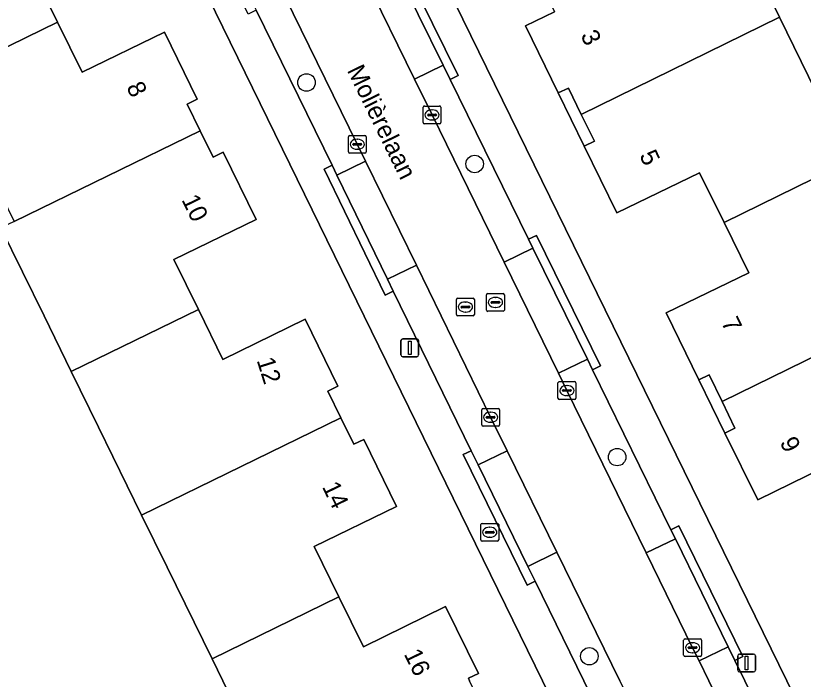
# Model space of a CAD drawing. Extents: x 160455 to 162082, y 388339 to 389736.
# Drawn here: x 160753.79 to 160797.83, y 388750.08 to 388787.22 of the extents above; entities that cross this region are included whole.
import ezdxf

# ---------------------------------------------------------------- set-up
doc = ezdxf.new("R2010")
doc.units = 0
for name, color, linetype in [('IMGEO_Boom', 7, 'Continuous'), ('IMGEO_Brandkraan', 7, 'Continuous'), ('IMGEO_Erf', 7, 'Continuous'), ('IMGEO_Kolk', 7, 'Continuous'), ('IMGEO_Lichtmast', 7, 'Continuous'), ('IMGEO_Openbare_ruimte_label', 7, 'Continuous'), ('IMGEO_Pand', 7, 'Continuous'), ('IMGEO_Pand_nummerreeks', 7, 'Continuous'), ('IMGEO_Parkeervlak_open', 7, 'Continuous'), ('IMGEO_Rijbaan_lokaal_gesloten', 7, 'Continuous'), ('IMGEO_Rioolput', 7, 'Continuous'), ('IMGEO_Voetpad_open', 7, 'Continuous')]:
    doc.layers.add(name, color=color, linetype=linetype)

msp = doc.modelspace()

# ---------------------------------------------------------------- linework, layer by layer
at = {"layer": 'IMGEO_Boom'}
for centre in [(160770.047, 388783.48), (160779.452, 388778.92), (160787.418, 388762.516), (160785.861, 388751.371)]:
    msp.add_circle(centre, 0.489, dxfattribs=at)
at = {"layer": 'IMGEO_Brandkraan'}
for p, q in [((160779.793, 388757.883), (160779.793, 388758.735)), ((160779.868, 388758.809), (160780.72, 388758.809)), ((160780.794, 388758.735), (160780.794, 388757.883)), ((160780.052, 388758.303), (160780.052, 388758.315)), ((160780.49, 388758.266), (160780.092, 388758.266)), ((160780.095, 388758.352), (160780.493, 388758.352)), ((160780.281, 388758.589), (160780.306, 388758.589)), ((160780.536, 388758.315), (160780.536, 388758.303)), ((160780.72, 388757.809), (160779.868, 388757.809)), ((160780.304, 388758.029), (160780.279, 388758.029))]:
    msp.add_line(p, q, dxfattribs=at)
for points in [[(160779.793, 388757.883), (160779.793, 388758.735)], [(160779.868, 388758.809), (160780.72, 388758.809)], [(160780.794, 388758.735), (160780.794, 388757.883)], [(160780.72, 388757.809), (160779.868, 388757.809)]]:
    msp.add_lwpolyline(points, dxfattribs=at)
for centre, radius, start, end in [((160779.87, 388758.733), 0.0765, 91.552, 178.448), ((160779.87, 388758.733), 0.0765, 91.552, 178.448), ((160780.718, 388758.733), 0.0765, 1.552, 88.448), ((160780.718, 388758.733), 0.0765, 1.552, 88.448), ((160780.092, 388758.312), 0.0403, 85.8775, 175.7526), ((160780.089, 388758.302), 0.0366, 178.938, 274.7102), ((160780.493, 388758.309), 0.043, 264.8664, 352.4533), ((160780.497, 388758.314), 0.0386, 1.7309, 96.639), ((160779.87, 388757.885), 0.0765, 181.552, 268.448), ((160779.87, 388757.885), 0.0765, 181.552, 268.448), ((160780.718, 388757.885), 0.0765, 271.552, 358.448), ((160780.718, 388757.885), 0.0765, 271.552, 358.448)]:
    msp.add_arc(centre, radius, start, end, dxfattribs=at)
for centre, major_axis, ratio, start_param, end_param in [((160780.28, 388758.309), (-0.387, 0.002), 0.722429, 4.712389, 7.853982), ((160780.305, 388758.309), (-0.39, 0.002), 0.717154, 1.570796, 4.712389)]:
    msp.add_ellipse(centre, major_axis=major_axis, ratio=ratio, start_param=start_param, end_param=end_param, dxfattribs=at)
at = {"layer": 'IMGEO_Erf'}
for points in [[(160762.403, 388820.913), (160762.283, 388820.813), (160769.045, 388806.982), (160773.503, 388797.864), (160796.902, 388750), (160806.284, 388730.808)], [(160798.94, 388717.887), (160783.242, 388750), (160751.22, 388815.507)], [(160794.101, 388792.028), (160796.497, 388787.131), (160798.923, 388782.173)], [(160754.753, 388789.659), (160756.132, 388786.849), (160757.504, 388784.052), (160762.105, 388786.298), (160763.937, 388782.546), (160763.371, 388782.269), (160764.101, 388780.783), (160764.824, 388779.31), (160765.39, 388779.587), (160767.23, 388775.821), (160762.63, 388773.573), (160763.999, 388770.779), (160765.372, 388767.978), (160769.972, 388770.227), (160771.803, 388766.479), (160771.237, 388766.202), (160771.966, 388764.711), (160772.688, 388763.234), (160773.254, 388763.51), (160775.082, 388759.759), (160770.479, 388757.517), (160771.857, 388754.704), (160773.231, 388751.898), (160777.828, 388754.153), (160779.662, 388750.414), (160779.097, 388750.136), (160779.163, 388750)], [(160799.891, 388762.386), (160795.278, 388760.118), (160793.436, 388763.863), (160791.989, 388766.839), (160790.163, 388770.583), (160794.784, 388772.835), (160793.401, 388775.643), (160792.029, 388778.429), (160787.408, 388776.179), (160785.583, 388779.926), (160784.123, 388782.893), (160782.292, 388786.652), (160783.913, 388787.442)], [(160778.747, 388724.517), (160777.293, 388727.489), (160774.889, 388732.4), (160774.153, 388732.04), (160772.633, 388735.146), (160770.115, 388740.29), (160772.314, 388741.367), (160770.895, 388744.266), (160768.487, 388749.186), (160766.288, 388748.11), (160765.363, 388750), (160764.763, 388751.225), (160762.25, 388756.361), (160760.825, 388759.272), (160758.418, 388764.189), (160756.893, 388767.305), (160755.369, 388770.42), (160752.96, 388775.341)]]:
    msp.add_lwpolyline(points, dxfattribs=at)
for points in [[(160785.583, 388779.926), (160786.149, 388780.202), (160785.414, 388781.697), (160784.69, 388783.169), (160784.123, 388782.893)], [(160793.436, 388763.863), (160794.002, 388764.141), (160793.282, 388765.62), (160792.555, 388767.115), (160791.989, 388766.839)]]:
    msp.add_lwpolyline(points, close=True, dxfattribs=at)
at = {"layer": 'IMGEO_Kolk'}
for p, q in [((160776.566, 388781.239), (160776.566, 388782.091)), ((160776.641, 388782.165), (160777.493, 388782.165)), ((160777.567, 388782.091), (160777.567, 388781.239)), ((160776.825, 388781.659), (160776.825, 388781.671)), ((160777.263, 388781.622), (160776.865, 388781.622)), ((160776.868, 388781.708), (160777.266, 388781.708)), ((160777.054, 388781.945), (160777.079, 388781.945)), ((160777.309, 388781.671), (160777.309, 388781.659)), ((160777.493, 388781.165), (160776.641, 388781.165)), ((160777.077, 388781.385), (160777.052, 388781.385)), ((160772.387, 388779.595), (160772.387, 388780.447)), ((160772.462, 388780.521), (160773.314, 388780.521)), ((160772.875, 388780.301), (160772.9, 388780.301)), ((160773.388, 388780.447), (160773.388, 388779.595)), ((160772.646, 388780.015), (160772.646, 388780.027)), ((160773.084, 388779.978), (160772.686, 388779.978)), ((160772.689, 388780.064), (160773.087, 388780.064)), ((160773.13, 388780.027), (160773.13, 388780.015)), ((160773.314, 388779.521), (160772.462, 388779.521)), ((160772.898, 388779.741), (160772.873, 388779.741)), ((160784.11, 388765.814), (160784.11, 388766.666)), ((160784.185, 388766.74), (160785.037, 388766.74)), ((160785.111, 388766.666), (160785.111, 388765.814)), ((160784.369, 388766.234), (160784.369, 388766.246)), ((160784.807, 388766.197), (160784.409, 388766.197)), ((160784.412, 388766.283), (160784.81, 388766.283)), ((160784.598, 388766.52), (160784.623, 388766.52)), ((160784.853, 388766.246), (160784.853, 388766.234)), ((160785.037, 388765.74), (160784.185, 388765.74)), ((160784.621, 388765.96), (160784.596, 388765.96)), ((160779.844, 388764.318), (160779.844, 388765.17)), ((160779.919, 388765.244), (160780.771, 388765.244)), ((160780.332, 388765.024), (160780.357, 388765.024)), ((160780.845, 388765.17), (160780.845, 388764.318)), ((160780.103, 388764.738), (160780.103, 388764.75)), ((160780.541, 388764.701), (160780.143, 388764.701)), ((160780.146, 388764.787), (160780.544, 388764.787)), ((160780.355, 388764.464), (160780.33, 388764.464)), ((160780.587, 388764.75), (160780.587, 388764.738)), ((160780.771, 388764.244), (160779.919, 388764.244)), ((160791.138, 388751.424), (160791.138, 388752.276)), ((160791.213, 388752.35), (160792.065, 388752.35)), ((160791.626, 388752.13), (160791.651, 388752.13)), ((160792.139, 388752.276), (160792.139, 388751.424)), ((160791.397, 388751.844), (160791.397, 388751.856)), ((160791.835, 388751.807), (160791.437, 388751.807)), ((160791.44, 388751.893), (160791.838, 388751.893)), ((160791.881, 388751.856), (160791.881, 388751.844)), ((160792.065, 388751.35), (160791.213, 388751.35)), ((160791.649, 388751.57), (160791.624, 388751.57))]:
    msp.add_line(p, q, dxfattribs=at)
for points in [[(160776.566, 388781.239), (160776.566, 388782.091)], [(160776.641, 388782.165), (160777.493, 388782.165)], [(160777.567, 388782.091), (160777.567, 388781.239)], [(160777.493, 388781.165), (160776.641, 388781.165)], [(160772.387, 388779.595), (160772.387, 388780.447)], [(160772.462, 388780.521), (160773.314, 388780.521)], [(160773.388, 388780.447), (160773.388, 388779.595)], [(160773.314, 388779.521), (160772.462, 388779.521)], [(160784.11, 388765.814), (160784.11, 388766.666)], [(160784.185, 388766.74), (160785.037, 388766.74)], [(160785.111, 388766.666), (160785.111, 388765.814)], [(160785.037, 388765.74), (160784.185, 388765.74)], [(160779.844, 388764.318), (160779.844, 388765.17)], [(160779.919, 388765.244), (160780.771, 388765.244)], [(160780.845, 388765.17), (160780.845, 388764.318)], [(160780.771, 388764.244), (160779.919, 388764.244)], [(160791.138, 388751.424), (160791.138, 388752.276)], [(160791.213, 388752.35), (160792.065, 388752.35)], [(160792.139, 388752.276), (160792.139, 388751.424)], [(160792.065, 388751.35), (160791.213, 388751.35)]]:
    msp.add_lwpolyline(points, dxfattribs=at)
for centre, radius, start, end in [((160776.643, 388782.089), 0.0765, 91.552, 178.448), ((160776.643, 388782.089), 0.0765, 91.552, 178.448), ((160777.491, 388782.089), 0.0765, 1.552, 88.448), ((160777.491, 388782.089), 0.0765, 1.552, 88.448), ((160776.865, 388781.668), 0.0403, 85.8775, 175.7526), ((160776.862, 388781.658), 0.0366, 178.938, 274.7102), ((160777.266, 388781.665), 0.043, 264.8664, 352.4533), ((160777.27, 388781.67), 0.0386, 1.7309, 96.639), ((160776.643, 388781.241), 0.0765, 181.552, 268.448), ((160776.643, 388781.241), 0.0765, 181.552, 268.448), ((160777.491, 388781.241), 0.0765, 271.552, 358.448), ((160777.491, 388781.241), 0.0765, 271.552, 358.448), ((160772.464, 388780.445), 0.0765, 91.552, 178.448), ((160772.464, 388780.445), 0.0765, 91.552, 178.448), ((160773.312, 388780.445), 0.0765, 1.552, 88.448), ((160773.312, 388780.445), 0.0765, 1.552, 88.448), ((160772.686, 388780.024), 0.0403, 85.8775, 175.7526), ((160772.683, 388780.014), 0.0366, 178.938, 274.7102), ((160773.087, 388780.021), 0.043, 264.8664, 352.4533), ((160773.091, 388780.026), 0.0386, 1.7309, 96.639), ((160772.464, 388779.597), 0.0765, 181.552, 268.448), ((160772.464, 388779.597), 0.0765, 181.552, 268.448), ((160773.312, 388779.597), 0.0765, 271.552, 358.448), ((160773.312, 388779.597), 0.0765, 271.552, 358.448), ((160784.187, 388766.664), 0.0765, 91.552, 178.448), ((160784.187, 388766.664), 0.0765, 91.552, 178.448), ((160785.035, 388766.664), 0.0765, 1.552, 88.448), ((160785.035, 388766.664), 0.0765, 1.552, 88.448), ((160784.409, 388766.243), 0.0403, 85.8775, 175.7526), ((160784.406, 388766.233), 0.0366, 178.938, 274.7102), ((160784.81, 388766.24), 0.043, 264.8664, 352.4533), ((160784.814, 388766.245), 0.0386, 1.7309, 96.639), ((160784.187, 388765.816), 0.0765, 181.552, 268.448), ((160784.187, 388765.816), 0.0765, 181.552, 268.448), ((160785.035, 388765.816), 0.0765, 271.552, 358.448), ((160785.035, 388765.816), 0.0765, 271.552, 358.448), ((160779.921, 388765.168), 0.0765, 91.552, 178.448), ((160779.921, 388765.168), 0.0765, 91.552, 178.448), ((160780.769, 388765.168), 0.0765, 1.552, 88.448), ((160780.769, 388765.168), 0.0765, 1.552, 88.448), ((160780.143, 388764.747), 0.0403, 85.8775, 175.7526), ((160780.14, 388764.737), 0.0366, 178.938, 274.7102), ((160780.544, 388764.744), 0.043, 264.8664, 352.4533), ((160780.548, 388764.749), 0.0386, 1.7309, 96.639), ((160779.921, 388764.32), 0.0765, 181.552, 268.448), ((160779.921, 388764.32), 0.0765, 181.552, 268.448), ((160780.769, 388764.32), 0.0765, 271.552, 358.448), ((160780.769, 388764.32), 0.0765, 271.552, 358.448), ((160791.215, 388752.274), 0.0765, 91.552, 178.448), ((160791.215, 388752.274), 0.0765, 91.552, 178.448), ((160792.063, 388752.274), 0.0765, 1.552, 88.448), ((160792.063, 388752.274), 0.0765, 1.552, 88.448), ((160791.437, 388751.853), 0.0403, 85.8775, 175.7526), ((160791.434, 388751.843), 0.0366, 178.938, 274.7102), ((160791.838, 388751.85), 0.043, 264.8664, 352.4533), ((160791.842, 388751.855), 0.0386, 1.7309, 96.639), ((160791.215, 388751.426), 0.0765, 181.552, 268.448), ((160791.215, 388751.426), 0.0765, 181.552, 268.448), ((160792.063, 388751.426), 0.0765, 271.552, 358.448), ((160792.063, 388751.426), 0.0765, 271.552, 358.448)]:
    msp.add_arc(centre, radius, start, end, dxfattribs=at)
for centre, major_axis, ratio, start_param, end_param in [((160777.053, 388781.665), (-0.387, 0.002), 0.722429, 4.712389, 7.853982), ((160777.078, 388781.665), (-0.39, 0.002), 0.717154, 1.570796, 4.712389), ((160772.874, 388780.021), (-0.387, 0.002), 0.722429, 4.712389, 7.853982), ((160772.899, 388780.021), (-0.39, 0.002), 0.717154, 1.570796, 4.712389), ((160784.597, 388766.24), (-0.387, 0.002), 0.722429, 4.712389, 7.853982), ((160784.622, 388766.24), (-0.39, 0.002), 0.717154, 1.570796, 4.712389), ((160780.331, 388764.744), (-0.387, 0.002), 0.722429, 4.712389, 7.853982), ((160780.356, 388764.744), (-0.39, 0.002), 0.717154, 1.570796, 4.712389), ((160791.625, 388751.85), (-0.387, 0.002), 0.722429, 4.712389, 7.853982), ((160791.65, 388751.85), (-0.39, 0.002), 0.717154, 1.570796, 4.712389)]:
    msp.add_ellipse(centre, major_axis=major_axis, ratio=ratio, start_param=start_param, end_param=end_param, dxfattribs=at)
at = {"layer": 'IMGEO_Lichtmast'}
for p, q in [((160775.329, 388768.235), (160775.329, 388769.035)), ((160775.329, 388769.035), (160775.329, 388768.235)), ((160775.429, 388769.135), (160776.219, 388769.135)), ((160776.219, 388769.135), (160775.429, 388769.135)), ((160776.319, 388769.035), (160776.319, 388768.235)), ((160776.319, 388768.235), (160776.319, 388769.035)), ((160776.219, 388768.135), (160775.429, 388768.135)), ((160775.429, 388768.135), (160776.219, 388768.135)), ((160794.158, 388750.593), (160794.158, 388751.393)), ((160794.158, 388751.393), (160794.158, 388750.593)), ((160794.258, 388751.493), (160795.048, 388751.493)), ((160795.048, 388751.493), (160794.258, 388751.493)), ((160795.148, 388751.393), (160795.148, 388750.593)), ((160795.148, 388750.593), (160795.148, 388751.393)), ((160795.048, 388750.493), (160794.258, 388750.493)), ((160794.258, 388750.493), (160795.048, 388750.493))]:
    msp.add_line(p, q, dxfattribs=at)
for points in [[(160775.749, 388769.01), (160775.899, 388769.01), (160775.899, 388768.26), (160775.749, 388768.26), (160775.749, 388769.01)], [(160794.578, 388751.368), (160794.728, 388751.368), (160794.728, 388750.618), (160794.578, 388750.618), (160794.578, 388751.368)]]:
    msp.add_lwpolyline(points, dxfattribs=at)
for centre, start, end in [((160775.429, 388769.035), 90, 180), ((160775.429, 388769.035), 90, 180), ((160776.219, 388769.035), 0, 90), ((160776.219, 388769.035), 360, 90), ((160775.429, 388768.235), 180, 270), ((160775.429, 388768.235), 180, 270), ((160776.219, 388768.235), 270, 0), ((160776.219, 388768.235), 270, 0), ((160794.258, 388751.393), 90, 180), ((160794.258, 388751.393), 90, 180), ((160795.048, 388751.393), 0, 90), ((160795.048, 388751.393), 360, 90), ((160794.258, 388750.593), 180, 270), ((160794.258, 388750.593), 180, 270), ((160795.048, 388750.593), 270, 0), ((160795.048, 388750.593), 270, 0)]:
    msp.add_arc(centre, 0.1, start, end, dxfattribs=at)
at = {"layer": 'IMGEO_Pand'}
for points in [[(160749.025, 388783.384), (160756.132, 388786.849), (160754.753, 388789.659), (160759.355, 388791.904), (160757.521, 388795.663), (160756.954, 388795.387), (160756.237, 388796.855), (160747.282, 388792.491), (160749.69, 388787.572), (160747.5, 388786.499)], [(160792.571, 388795.154), (160785.541, 388791.701), (160782.547, 388790.23), (160783.913, 388787.442), (160782.292, 388786.652), (160784.123, 388782.893), (160784.69, 388783.169), (160785.414, 388781.697), (160796.497, 388787.131), (160794.101, 388792.028)], [(160749.025, 388783.384), (160751.538, 388778.249), (160752.274, 388778.609), (160753.697, 388775.7), (160764.101, 388780.783), (160763.371, 388782.269), (160763.937, 388782.546), (160762.105, 388786.298), (160757.504, 388784.052), (160756.132, 388786.849)], [(160796.497, 388787.131), (160785.414, 388781.697), (160786.149, 388780.202), (160785.583, 388779.926), (160787.408, 388776.179), (160792.029, 388778.429), (160793.401, 388775.643), (160800.43, 388779.094), (160798.923, 388782.173)], [(160756.893, 388767.305), (160763.999, 388770.779), (160762.63, 388773.573), (160767.23, 388775.821), (160765.39, 388779.587), (160764.824, 388779.31), (160764.101, 388780.783), (160753.697, 388775.7), (160752.96, 388775.341), (160755.369, 388770.42)], [(160793.401, 388775.643), (160794.784, 388772.835), (160790.163, 388770.583), (160791.989, 388766.839), (160792.555, 388767.115), (160793.282, 388765.62), (160804.365, 388771.054), (160801.966, 388775.955), (160800.43, 388779.094)], [(160804.365, 388771.054), (160793.282, 388765.62), (160794.002, 388764.141), (160793.436, 388763.863), (160795.278, 388760.118), (160799.891, 388762.386), (160801.263, 388759.574), (160808.294, 388763.025), (160811.219, 388764.461), (160807.288, 388772.495)], [(160756.893, 388767.305), (160758.418, 388764.189), (160760.825, 388759.272), (160771.966, 388764.711), (160771.237, 388766.202), (160771.803, 388766.479), (160769.972, 388770.227), (160765.372, 388767.978), (160763.999, 388770.779)], [(160771.857, 388754.704), (160770.479, 388757.517), (160775.082, 388759.759), (160773.254, 388763.51), (160772.688, 388763.234), (160771.966, 388764.711), (160760.825, 388759.272), (160762.25, 388756.361), (160764.763, 388751.225)], [(160771.857, 388754.704), (160764.763, 388751.225), (160765.363, 388750), (160766.288, 388748.11), (160768.487, 388749.186), (160770.895, 388744.266), (160779.827, 388748.636), (160779.163, 388750), (160779.097, 388750.136), (160779.662, 388750.414), (160777.828, 388754.153), (160773.231, 388751.898)]]:
    msp.add_lwpolyline(points, close=True, dxfattribs=at)
at = {"layer": 'IMGEO_Parkeervlak_open'}
for points in [[(160774.897, 388790.136), (160773.301, 388789.354), (160776.082, 388783.674), (160777.681, 388784.457)], [(160768.406, 388789.196), (160766.803, 388788.413), (160767.24, 388787.521), (160771.476, 388778.85), (160771.742, 388778.301), (160773.346, 388779.084), (160772.889, 388780.021)], [(160778.078, 388783.647), (160777.681, 388784.457), (160776.082, 388783.674), (160777.066, 388781.664), (160781.099, 388773.419), (160782.707, 388774.206), (160782.463, 388774.704)], [(160773.346, 388779.084), (160771.742, 388778.301), (160774.575, 388772.466), (160776.191, 388773.256)], [(160782.707, 388774.206), (160781.099, 388773.419), (160784.136, 388767.21), (160785.752, 388768)], [(160776.191, 388773.256), (160774.575, 388772.466), (160774.898, 388771.8), (160779.263, 388762.876), (160779.654, 388762.076), (160781.266, 388762.866), (160780.345, 388764.745)], [(160786.046, 388767.401), (160785.752, 388768), (160784.136, 388767.21), (160784.61, 388766.24), (160789.047, 388757.155), (160790.673, 388757.95), (160790.427, 388758.453)], [(160781.266, 388762.866), (160779.654, 388762.076), (160782.431, 388756.399), (160784.046, 388757.191)], [(160790.673, 388757.95), (160789.047, 388757.155), (160791.638, 388751.849), (160792, 388751.11), (160793.623, 388751.905)], [(160784.046, 388757.191), (160782.431, 388756.399), (160782.839, 388755.564), (160785.561, 388750), (160787.221, 388746.607), (160787.583, 388745.867), (160789.2, 388746.653), (160787.869, 388749.389), (160787.57, 388750)], [(160794.551, 388750), (160794, 388751.132), (160793.623, 388751.905), (160792, 388751.11), (160792.544, 388750), (160797.021, 388740.864), (160798.623, 388741.649), (160798.231, 388742.445)]]:
    msp.add_lwpolyline(points, close=True, dxfattribs=at)
at = {"layer": 'IMGEO_Rijbaan_lokaal_gesloten'}
for points in [[(160768.406, 388789.196), (160772.889, 388780.021), (160773.346, 388779.084), (160776.191, 388773.256), (160780.345, 388764.745), (160781.266, 388762.866), (160784.046, 388757.191), (160787.57, 388750), (160787.869, 388749.389), (160789.2, 388746.653), (160792.011, 388740.874), (160795.768, 388733.152), (160796.496, 388731.738), (160796.586, 388731.565), (160800.932, 388722.63)], [(160799.905, 388734.979), (160797.021, 388740.864), (160792.544, 388750), (160792, 388751.11), (160791.638, 388751.849), (160789.047, 388757.155), (160784.61, 388766.24), (160784.136, 388767.21), (160781.099, 388773.419), (160777.066, 388781.664), (160776.082, 388783.674), (160773.301, 388789.354)]]:
    msp.add_lwpolyline(points, dxfattribs=at)
at = {"layer": 'IMGEO_Rioolput'}
for p, q in [((160778.509, 388771.416), (160779.361, 388771.416)), ((160780.111, 388770.748), (160780.111, 388771.6)), ((160780.186, 388771.674), (160781.038, 388771.674)), ((160780.599, 388771.454), (160780.624, 388771.454)), ((160781.112, 388771.6), (160781.112, 388770.748)), ((160778.434, 388770.49), (160778.434, 388771.342)), ((160778.922, 388771.196), (160778.947, 388771.196)), ((160779.435, 388771.342), (160779.435, 388770.49)), ((160780.37, 388771.168), (160780.37, 388771.18)), ((160780.808, 388771.131), (160780.41, 388771.131)), ((160780.413, 388771.217), (160780.811, 388771.217)), ((160780.854, 388771.18), (160780.854, 388771.168)), ((160778.693, 388770.91), (160778.693, 388770.922)), ((160779.131, 388770.873), (160778.733, 388770.873)), ((160778.736, 388770.959), (160779.134, 388770.959)), ((160778.945, 388770.636), (160778.92, 388770.636)), ((160779.177, 388770.922), (160779.177, 388770.91)), ((160781.038, 388770.674), (160780.186, 388770.674)), ((160780.622, 388770.894), (160780.597, 388770.894)), ((160779.361, 388770.416), (160778.509, 388770.416))]:
    msp.add_line(p, q, dxfattribs=at)
for points in [[(160778.509, 388771.416), (160779.361, 388771.416)], [(160780.111, 388770.748), (160780.111, 388771.6)], [(160780.186, 388771.674), (160781.038, 388771.674)], [(160781.112, 388771.6), (160781.112, 388770.748)], [(160778.434, 388770.49), (160778.434, 388771.342)], [(160779.435, 388771.342), (160779.435, 388770.49)], [(160781.038, 388770.674), (160780.186, 388770.674)], [(160779.361, 388770.416), (160778.509, 388770.416)]]:
    msp.add_lwpolyline(points, dxfattribs=at)
for centre, radius, start, end in [((160778.511, 388771.34), 0.0765, 91.552, 178.448), ((160778.511, 388771.34), 0.0765, 91.552, 178.448), ((160779.359, 388771.34), 0.0765, 1.552, 88.448), ((160779.359, 388771.34), 0.0765, 1.552, 88.448), ((160780.188, 388771.598), 0.0765, 91.552, 178.448), ((160780.188, 388771.598), 0.0765, 91.552, 178.448), ((160781.036, 388771.598), 0.0765, 1.552, 88.448), ((160781.036, 388771.598), 0.0765, 1.552, 88.448), ((160780.41, 388771.177), 0.0403, 85.8775, 175.7526), ((160780.407, 388771.167), 0.0366, 178.938, 274.7102), ((160780.811, 388771.174), 0.043, 264.8664, 352.4533), ((160780.815, 388771.179), 0.0386, 1.7309, 96.639), ((160778.733, 388770.919), 0.0403, 85.8775, 175.7526), ((160778.73, 388770.909), 0.0366, 178.938, 274.7102), ((160779.134, 388770.916), 0.043, 264.8664, 352.4533), ((160779.138, 388770.921), 0.0386, 1.7309, 96.639), ((160780.188, 388770.75), 0.0765, 181.552, 268.448), ((160780.188, 388770.75), 0.0765, 181.552, 268.448), ((160781.036, 388770.75), 0.0765, 271.552, 358.448), ((160781.036, 388770.75), 0.0765, 271.552, 358.448), ((160778.511, 388770.492), 0.0765, 181.552, 268.448), ((160778.511, 388770.492), 0.0765, 181.552, 268.448), ((160779.359, 388770.492), 0.0765, 271.552, 358.448), ((160779.359, 388770.492), 0.0765, 271.552, 358.448)]:
    msp.add_arc(centre, radius, start, end, dxfattribs=at)
for centre, major_axis, ratio, start_param, end_param in [((160780.598, 388771.174), (-0.387, 0.002), 0.722429, 4.712389, 7.853982), ((160780.623, 388771.174), (-0.39, 0.002), 0.717154, 1.570796, 4.712389), ((160778.921, 388770.916), (-0.387, 0.002), 0.722429, 4.712389, 7.853982), ((160778.946, 388770.916), (-0.39, 0.002), 0.717154, 1.570796, 4.712389)]:
    msp.add_ellipse(centre, major_axis=major_axis, ratio=ratio, start_param=start_param, end_param=end_param, dxfattribs=at)
at = {"layer": 'IMGEO_Voetpad_open'}
for points in [[(160806.284, 388730.808), (160796.902, 388750), (160773.503, 388797.864), (160769.045, 388806.982), (160762.283, 388820.813), (160762.403, 388820.913)], [(160762.271, 388815.955), (160774.49, 388790.966), (160774.938, 388791.186), (160778.526, 388783.867), (160778.078, 388783.647), (160782.463, 388774.704), (160782.911, 388774.924), (160786.494, 388767.621), (160786.046, 388767.401), (160790.427, 388758.453), (160790.876, 388758.672), (160794.449, 388751.351), (160794, 388751.132), (160794.551, 388750), (160798.231, 388742.445), (160798.679, 388742.665), (160802.333, 388735.248), (160801.885, 388735.028)], [(160751.22, 388815.507), (160783.242, 388750), (160798.94, 388717.887), (160796.193, 388716.592), (160796.096, 388716.524), (160796.229, 388716.231), (160787.552, 388711.973), (160789.992, 388706.936), (160811.085, 388717.249), (160809.661, 388720.335), (160800.591, 388722.19), (160796.035, 388731.513), (160796.496, 388731.738)], [(160793.577, 388733.616), (160790.788, 388739.318), (160790.34, 388739.099), (160786.774, 388746.389), (160787.221, 388746.607), (160785.561, 388750), (160782.839, 388755.564), (160782.39, 388755.345), (160778.813, 388762.657), (160779.263, 388762.876), (160774.898, 388771.8), (160774.449, 388771.582), (160771.027, 388778.632), (160771.476, 388778.85), (160767.24, 388787.521), (160766.791, 388787.302), (160763.204, 388794.629), (160763.653, 388794.848), (160759.281, 388803.764), (160758.29, 388803.286), (160756.18, 388807.657), (160757.171, 388808.135), (160755.331, 388811.883)]]:
    msp.add_lwpolyline(points, dxfattribs=at)
for points in [[(160774.938, 388791.186), (160774.49, 388790.966), (160774.897, 388790.136), (160777.681, 388784.457), (160778.078, 388783.647), (160778.526, 388783.867)], [(160771.742, 388778.301), (160771.476, 388778.85), (160771.027, 388778.632), (160774.449, 388771.582), (160774.898, 388771.8), (160774.575, 388772.466)], [(160782.911, 388774.924), (160782.463, 388774.704), (160782.707, 388774.206), (160785.752, 388768), (160786.046, 388767.401), (160786.494, 388767.621)], [(160779.654, 388762.076), (160779.263, 388762.876), (160778.813, 388762.657), (160782.39, 388755.345), (160782.839, 388755.564), (160782.431, 388756.399)], [(160790.876, 388758.672), (160790.427, 388758.453), (160790.673, 388757.95), (160793.623, 388751.905), (160794, 388751.132), (160794.449, 388751.351)]]:
    msp.add_lwpolyline(points, close=True, dxfattribs=at)

# ---------------------------------------------------------------- texts
at = {"layer": 'IMGEO_Openbare_ruimte_label'}
msp.add_text('Molièrelaan', height=1, rotation=296.1553, dxfattribs=at).set_placement((160772.292, 388784.164))
at = {"layer": 'IMGEO_Pand_nummerreeks'}
for s, rotation, p in [('3', 295.972, (160785.353, 388786.123)), ('8', 296.025, (160759.955, 388783.227)), ('5', 295.9687, (160788.641, 388779.403)), ('10', 296.0393, (160763.041, 388776.922)), ('7', 295.9991, (160793.221, 388770.063)), ('12', 287.4472, (160767.254, 388767.936)), ('9', 296.1897, (160796.496, 388763.349)), ('14', 295.9817, (160770.898, 388760.858)), ('16', 296.1282, (160775.476, 388751.499))]:
    msp.add_text(s, height=1, rotation=rotation, dxfattribs=at).set_placement(p)

doc.saveas('drawing.dxf')
